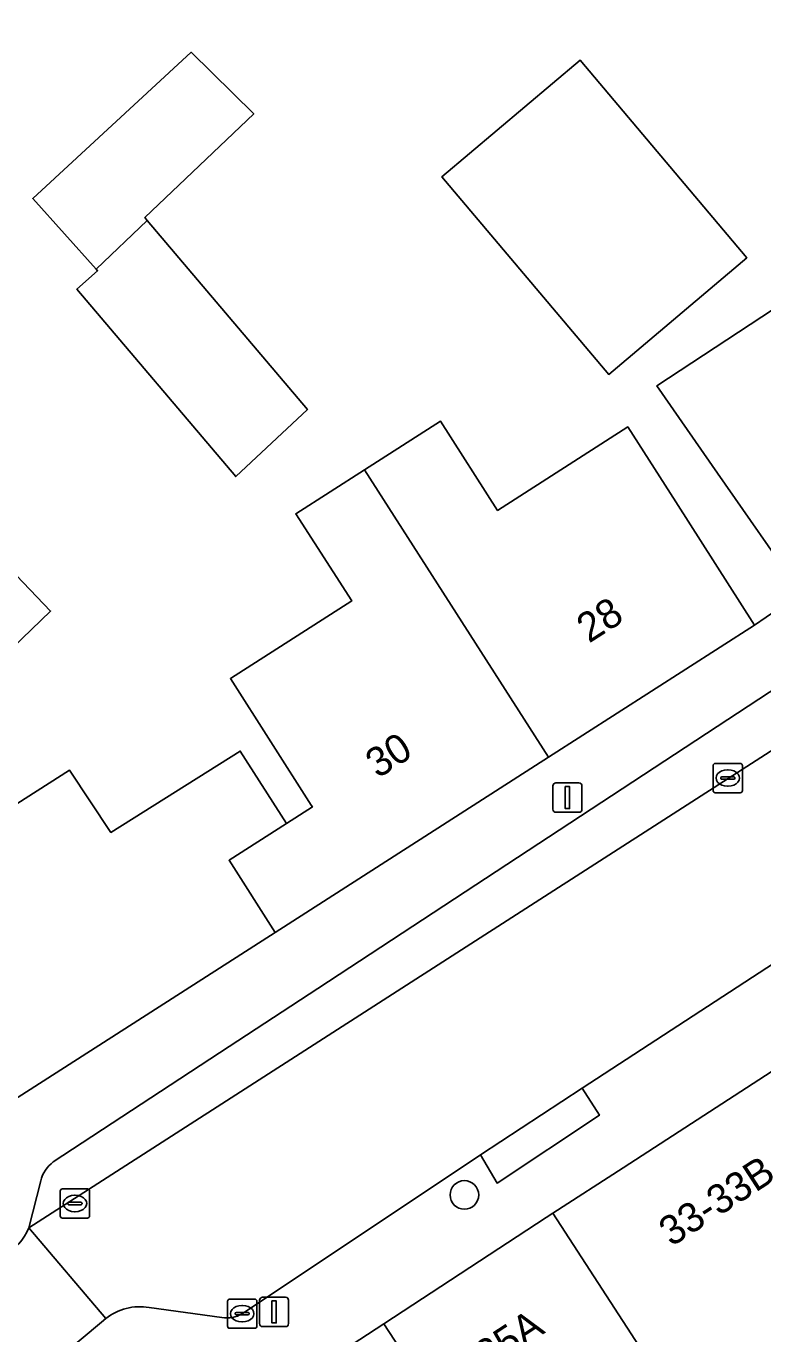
# Model space of a CAD drawing. Extents: x 161772 to 163126, y 383092 to 383917.
# Drawn here: x 162247.58 to 162272.75, y 383341.19 to 383385.86 of the extents above; entities that cross this region are included whole.
import ezdxf

# ---------------------------------------------------------------- set-up
doc = ezdxf.new("R2010")
doc.units = 0
for name, color, linetype in [('IMGEO_Boom', 7, 'Continuous'), ('IMGEO_Erf', 7, 'Continuous'), ('IMGEO_Kolk', 7, 'Continuous'), ('IMGEO_Lichtmast', 7, 'Continuous'), ('IMGEO_Pand', 7, 'Continuous'), ('IMGEO_Pand_nummerreeks', 7, 'Continuous'), ('IMGEO_Parkeervlak_open', 7, 'Continuous'), ('IMGEO_Rijbaan_lokaal_open', 7, 'Continuous'), ('IMGEO_Voetpad_open', 7, 'Continuous')]:
    doc.layers.add(name, color=color, linetype=linetype)

msp = doc.modelspace()

# ---------------------------------------------------------------- linework, layer by layer
at = {"layer": 'IMGEO_Boom'}
msp.add_circle((162262.557, 383345.937), 0.489, dxfattribs=at)
at = {"layer": 'IMGEO_Erf'}
for points in [[(162253.226, 383384.97), (162255.362, 383382.868), (162251.638, 383379.324), (162251.719, 383379.228), (162257.195, 383372.769), (162254.746, 383370.474), (162249.318, 383376.881), (162250.022, 383377.509), (162249.974, 383377.564), (162247.811, 383379.978)], [(162266.507, 383384.701), (162272.205, 383377.953), (162267.486, 383373.968), (162261.787, 383380.716)], [(162243.444, 383371.066), (162245.614, 383368.806), (162247.017, 383367.345), (162248.42, 383365.883), (162244.848, 383362.453), (162245.165, 383362.122), (162242.866, 383359.915), (162239.259, 383356.452), (162233.964, 383361.967), (162237.572, 383365.43), (162238.289, 383366.119)]]:
    msp.add_lwpolyline(points, close=True, dxfattribs=at)
msp.add_lwpolyline([(162246.15, 383358.588), (162249.06, 383360.453), (162250.478, 383358.321), (162254.9, 383361.102), (162256.478, 383358.625), (162257.361, 383359.19), (162257.323, 383359.251), (162254.561, 383363.573), (162258.706, 383366.228), (162256.796, 383369.209), (162259.141, 383370.711), (162261.734, 383372.372), (162263.689, 383369.321), (162268.136, 383372.17), (162269.776, 383369.611), (162272.473, 383365.4), (162274.058, 383366.492), (162271.202, 383370.596), (162269.13, 383373.573), (162276.666, 383378.534)], dxfattribs=at)
at = {"layer": 'IMGEO_Kolk'}
for p, q in [((162271.054, 383359.752), (162271.054, 383360.604)), ((162271.129, 383360.678), (162271.981, 383360.678)), ((162271.542, 383360.458), (162271.567, 383360.458)), ((162272.055, 383360.604), (162272.055, 383359.752)), ((162271.313, 383360.172), (162271.313, 383360.184)), ((162271.751, 383360.135), (162271.353, 383360.135)), ((162271.356, 383360.221), (162271.754, 383360.221)), ((162271.797, 383360.184), (162271.797, 383360.172)), ((162271.981, 383359.678), (162271.129, 383359.678)), ((162271.565, 383359.898), (162271.54, 383359.898)), ((162248.825, 383346.145), (162249.677, 383346.145)), ((162248.75, 383345.219), (162248.75, 383346.071)), ((162249.009, 383345.639), (162249.009, 383345.651)), ((162249.052, 383345.688), (162249.45, 383345.688)), ((162249.238, 383345.925), (162249.263, 383345.925)), ((162249.493, 383345.651), (162249.493, 383345.639)), ((162249.751, 383346.071), (162249.751, 383345.219)), ((162249.447, 383345.602), (162249.049, 383345.602)), ((162249.261, 383345.365), (162249.236, 383345.365)), ((162249.677, 383345.145), (162248.825, 383345.145)), ((162254.464, 383341.456), (162254.464, 383342.308)), ((162254.539, 383342.382), (162255.391, 383342.382)), ((162254.952, 383342.162), (162254.977, 383342.162)), ((162255.465, 383342.308), (162255.465, 383341.456)), ((162254.723, 383341.876), (162254.723, 383341.888)), ((162255.161, 383341.839), (162254.763, 383341.839)), ((162254.766, 383341.925), (162255.164, 383341.925)), ((162255.207, 383341.888), (162255.207, 383341.876)), ((162255.391, 383341.382), (162254.539, 383341.382)), ((162254.975, 383341.602), (162254.95, 383341.602))]:
    msp.add_line(p, q, dxfattribs=at)
for points in [[(162271.054, 383359.752), (162271.054, 383360.604)], [(162271.129, 383360.678), (162271.981, 383360.678)], [(162272.055, 383360.604), (162272.055, 383359.752)], [(162271.981, 383359.678), (162271.129, 383359.678)], [(162248.825, 383346.145), (162249.677, 383346.145)], [(162248.75, 383345.219), (162248.75, 383346.071)], [(162249.751, 383346.071), (162249.751, 383345.219)], [(162249.677, 383345.145), (162248.825, 383345.145)], [(162254.464, 383341.456), (162254.464, 383342.308)], [(162254.539, 383342.382), (162255.391, 383342.382)], [(162255.465, 383342.308), (162255.465, 383341.456)], [(162255.391, 383341.382), (162254.539, 383341.382)]]:
    msp.add_lwpolyline(points, dxfattribs=at)
for centre, radius, start, end in [((162271.131, 383360.602), 0.0765, 91.552, 178.448), ((162271.131, 383360.602), 0.0765, 91.552, 178.448), ((162271.979, 383360.602), 0.0765, 1.552, 88.448), ((162271.979, 383360.602), 0.0765, 1.552, 88.448), ((162271.353, 383360.181), 0.0403, 85.8775, 175.7526), ((162271.35, 383360.171), 0.0366, 178.938, 274.7102), ((162271.754, 383360.178), 0.043, 264.8664, 352.4533), ((162271.758, 383360.183), 0.0386, 1.7309, 96.639), ((162271.131, 383359.754), 0.0765, 181.552, 268.448), ((162271.131, 383359.754), 0.0765, 181.552, 268.448), ((162271.979, 383359.754), 0.0765, 271.552, 358.448), ((162271.979, 383359.754), 0.0765, 271.552, 358.448), ((162248.827, 383346.069), 0.0765, 91.552, 178.448), ((162248.827, 383346.069), 0.0765, 91.552, 178.448), ((162249.675, 383346.069), 0.0765, 1.552, 88.448), ((162249.675, 383346.069), 0.0765, 1.552, 88.448), ((162249.049, 383345.648), 0.0403, 85.8775, 175.7526), ((162249.046, 383345.638), 0.0366, 178.938, 274.7102), ((162249.45, 383345.645), 0.043, 264.8664, 352.4533), ((162249.454, 383345.65), 0.0386, 1.7309, 96.639), ((162248.827, 383345.221), 0.0765, 181.552, 268.448), ((162248.827, 383345.221), 0.0765, 181.552, 268.448), ((162249.675, 383345.221), 0.0765, 271.552, 358.448), ((162249.675, 383345.221), 0.0765, 271.552, 358.448), ((162254.541, 383342.306), 0.0765, 91.552, 178.448), ((162254.541, 383342.306), 0.0765, 91.552, 178.448), ((162255.389, 383342.306), 0.0765, 1.552, 88.448), ((162255.389, 383342.306), 0.0765, 1.552, 88.448), ((162254.763, 383341.885), 0.0403, 85.8775, 175.7526), ((162254.76, 383341.875), 0.0366, 178.938, 274.7102), ((162255.164, 383341.882), 0.043, 264.8664, 352.4533), ((162255.168, 383341.887), 0.0386, 1.7309, 96.639), ((162254.541, 383341.458), 0.0765, 181.552, 268.448), ((162254.541, 383341.458), 0.0765, 181.552, 268.448), ((162255.389, 383341.458), 0.0765, 271.552, 358.448), ((162255.389, 383341.458), 0.0765, 271.552, 358.448)]:
    msp.add_arc(centre, radius, start, end, dxfattribs=at)
for centre, major_axis, ratio, start_param, end_param in [((162271.541, 383360.178), (-0.387, 0.002), 0.722429, 4.712389, 7.853982), ((162271.566, 383360.178), (-0.39, 0.002), 0.717154, 1.570796, 4.712389), ((162249.237, 383345.645), (-0.387, 0.002), 0.722429, 4.712389, 7.853982), ((162249.262, 383345.645), (-0.39, 0.002), 0.717154, 1.570796, 4.712389), ((162254.951, 383341.882), (-0.387, 0.002), 0.722429, 4.712389, 7.853982), ((162254.976, 383341.882), (-0.39, 0.002), 0.717154, 1.570796, 4.712389)]:
    msp.add_ellipse(centre, major_axis=major_axis, ratio=ratio, start_param=start_param, end_param=end_param, dxfattribs=at)
at = {"layer": 'IMGEO_Lichtmast'}
for p, q in [((162265.681, 383360.01), (162266.471, 383360.01)), ((162266.471, 383360.01), (162265.681, 383360.01)), ((162265.581, 383359.11), (162265.581, 383359.91)), ((162265.581, 383359.91), (162265.581, 383359.11)), ((162266.571, 383359.91), (162266.571, 383359.11)), ((162266.571, 383359.11), (162266.571, 383359.91)), ((162266.471, 383359.01), (162265.681, 383359.01)), ((162265.681, 383359.01), (162266.471, 383359.01)), ((162255.558, 383341.541), (162255.558, 383342.341)), ((162255.558, 383342.341), (162255.558, 383341.541)), ((162255.658, 383342.441), (162256.448, 383342.441)), ((162256.448, 383342.441), (162255.658, 383342.441)), ((162256.548, 383342.341), (162256.548, 383341.541)), ((162256.548, 383341.541), (162256.548, 383342.341)), ((162256.448, 383341.441), (162255.658, 383341.441)), ((162255.658, 383341.441), (162256.448, 383341.441))]:
    msp.add_line(p, q, dxfattribs=at)
for points in [[(162266.001, 383359.885), (162266.151, 383359.885), (162266.151, 383359.135), (162266.001, 383359.135), (162266.001, 383359.885)], [(162255.978, 383342.316), (162256.128, 383342.316), (162256.128, 383341.566), (162255.978, 383341.566), (162255.978, 383342.316)]]:
    msp.add_lwpolyline(points, dxfattribs=at)
for centre, start, end in [((162265.681, 383359.91), 90, 180), ((162265.681, 383359.91), 90, 180), ((162266.471, 383359.91), 0, 90), ((162266.471, 383359.91), 360, 90), ((162265.681, 383359.11), 180, 270), ((162265.681, 383359.11), 180, 270), ((162266.471, 383359.11), 270, 0), ((162266.471, 383359.11), 270, 0), ((162255.658, 383342.341), 90, 180), ((162255.658, 383342.341), 90, 180), ((162256.448, 383342.341), 0, 90), ((162256.448, 383342.341), 360, 90), ((162255.658, 383341.541), 180, 270), ((162255.658, 383341.541), 180, 270), ((162256.448, 383341.541), 270, 0), ((162256.448, 383341.541), 270, 0)]:
    msp.add_arc(centre, 0.1, start, end, dxfattribs=at)
at = {"layer": 'IMGEO_Pand'}
for points in [[(162249.974, 383377.564), (162251.719, 383379.228), (162251.638, 383379.324), (162255.362, 383382.868), (162253.226, 383384.97), (162247.811, 383379.978)], [(162267.486, 383373.968), (162272.205, 383377.953), (162266.507, 383384.701), (162261.787, 383380.716)], [(162249.974, 383377.564), (162250.022, 383377.509), (162249.318, 383376.881), (162254.746, 383370.474), (162257.195, 383372.769), (162251.719, 383379.228)], [(162279.486, 383374.316), (162276.955, 383378.161), (162276.666, 383378.534), (162269.13, 383373.573), (162271.202, 383370.596), (162274.058, 383366.492), (162281.53, 383371.212)], [(162265.432, 383360.889), (162272.473, 383365.4), (162269.776, 383369.611), (162268.136, 383372.17), (162263.689, 383369.321), (162261.734, 383372.372), (162259.141, 383370.711)], [(162245.165, 383362.122), (162244.848, 383362.453), (162248.42, 383365.883), (162247.017, 383367.345), (162245.614, 383368.806), (162243.444, 383371.066), (162238.289, 383366.119), (162237.572, 383365.43), (162233.964, 383361.967), (162239.259, 383356.452), (162242.866, 383359.915)], [(162259.141, 383370.711), (162256.796, 383369.209), (162258.706, 383366.228), (162254.561, 383363.573), (162257.323, 383359.251), (162257.361, 383359.19), (162256.478, 383358.625), (162254.519, 383357.371), (162256.096, 383354.907), (162265.432, 383360.889)], [(162256.478, 383358.625), (162254.9, 383361.102), (162250.478, 383358.321), (162249.06, 383360.453), (162246.15, 383358.588), (162240.626, 383355.049), (162245.995, 383349.427), (162247.147, 383349.174), (162256.096, 383354.907), (162254.519, 383357.371)], [(162273.27, 383350.29), (162267.982, 383346.867), (162265.576, 383345.313), (162270.362, 383337.946), (162272.569, 383339.386), (162275.024, 383335.763), (162276.007, 383334.264), (162279.166, 383336.333), (162281.626, 383337.944), (162281.137, 383338.698), (162280.649, 383339.452)], [(162268.478, 383336.717), (162268.836, 383336.95), (162270.362, 383337.946), (162265.576, 383345.313), (162265.346, 383345.166), (162259.802, 383341.536), (162267.119, 383330.346), (162267.972, 383329.029), (162270.071, 383325.787), (162271.515, 383324.106), (162273.769, 383326.031), (162274.339, 383326.466), (162271.249, 383331.172), (162270.66, 383331.129), (162269.2, 383333.319), (162270.276, 383334.021)], [(162259.802, 383341.536), (162253.701, 383337.545), (162253.9, 383337.318), (162262.568, 383327.401), (162267.119, 383330.346)]]:
    msp.add_lwpolyline(points, close=True, dxfattribs=at)
at = {"layer": 'IMGEO_Parkeervlak_open'}
for points in [[(162247.678, 383344.816), (162294.06, 383374.608)], [(162281.593, 383368.76), (162257.543, 383352.991)], [(162257.543, 383352.991), (162254.518, 383351.008)], [(162254.518, 383351.008), (162248.509, 383347.068)], [(162248.086, 383346.419), (162247.678, 383344.816)]]:
    msp.add_lwpolyline(points, dxfattribs=at)
msp.add_arc((162249.166, 383346.178), 1.106, 126.408, 167.4017, dxfattribs=at)
at = {"layer": 'IMGEO_Rijbaan_lokaal_open'}
for points in [[(162354.163, 383426.013), (162352.175, 383424.284), (162348.197, 383420.829), (162337.817, 383411.925), (162336.645, 383410.915), (162332.617, 383407.444), (162321.815, 383398.151), (162317.816, 383394.703), (162314.712, 383392.04), (162310.37, 383388.302), (162309.749, 383387.68), (162297.572, 383377.466), (162294.06, 383374.608), (162247.678, 383344.816), (162250.301, 383341.713)], [(162263.102, 383347.309), (162266.585, 383349.589), (162273.903, 383354.359), (162280.472, 383358.642), (162288.762, 383364.047), (162289.496, 383364.525), (162292.841, 383366.706), (162295.846, 383368.569), (162297.678, 383369.705), (162302.316, 383372.966), (162307.742, 383378.84), (162312.426, 383383.912), (162313.87, 383385.476), (162314.36, 383385.9), (162346.097, 383413.353)], [(162254.965, 383341.882), (162263.102, 383347.309)], [(162238.381, 383333.192), (162248.767, 383340.426), (162250.161, 383341.595), (162250.301, 383341.713), (162247.678, 383344.816)], [(162251.787, 383342.096), (162254.268, 383341.757)]]:
    msp.add_lwpolyline(points, dxfattribs=at)
for centre, radius, start, end in [((162245.851, 383345.597), 1.987, 299.2852, 336.8602), ((162251.479, 383340.218), 1.903, 80.6758, 128.2298), ((162254.461, 383342.684), 0.947, 258.2221, 302.1126)]:
    msp.add_arc(centre, radius, start, end, dxfattribs=at)
at = {"layer": 'IMGEO_Voetpad_open'}
for points in [[(162253.701, 383337.545), (162259.802, 383341.536), (162265.346, 383345.166), (162265.576, 383345.313), (162267.982, 383346.867), (162273.27, 383350.29), (162277.606, 383353.097), (162280.334, 383354.918), (162286.046, 383358.641), (162293.817, 383363.705), (162293.909, 383363.765), (162299.693, 383367.539), (162300.246, 383366.973), (162303.367, 383369.986), (162303.684, 383369.717), (162307.098, 383372.957), (162310.48, 383376.63), (162315.096, 383381.379), (162318.405, 383382.124), (162328.478, 383391.862)], [(162314.36, 383385.9), (162313.87, 383385.476), (162312.426, 383383.912), (162313.161, 383383.294), (162308.468, 383378.157), (162307.742, 383378.84), (162302.316, 383372.966), (162297.678, 383369.705), (162295.846, 383368.569), (162296.355, 383367.718), (162289.304, 383363.189), (162288.762, 383364.047), (162280.472, 383358.642), (162281.061, 383357.705), (162274.467, 383353.437), (162273.903, 383354.359), (162266.585, 383349.589), (162267.167, 383348.658), (162263.674, 383346.344), (162263.102, 383347.309), (162254.965, 383341.882)], [(162297.545, 383380.677), (162296.373, 383382.529), (162295.862, 383382.133), (162293.293, 383380.139), (162284.036, 383372.968), (162281.53, 383371.212), (162274.058, 383366.492), (162272.473, 383365.4), (162265.432, 383360.889), (162256.096, 383354.907), (162247.147, 383349.174), (162243.372, 383346.601), (162240.594, 383344.436)], [(162248.509, 383347.068), (162254.518, 383351.008), (162257.543, 383352.991), (162281.593, 383368.76), (162280.952, 383369.701)], [(162247.678, 383344.816), (162248.086, 383346.419)], [(162254.268, 383341.757), (162251.787, 383342.096)], [(162250.301, 383341.713), (162250.161, 383341.595), (162248.767, 383340.426)]]:
    msp.add_lwpolyline(points, dxfattribs=at)
msp.add_lwpolyline([(162263.102, 383347.309), (162263.674, 383346.344), (162267.167, 383348.658), (162266.585, 383349.589)], close=True, dxfattribs=at)
for centre, radius, start, end in [((162249.166, 383346.178), 1.106, 126.408, 167.4017), ((162245.851, 383345.597), 1.987, 299.2852, 336.8602), ((162251.479, 383340.218), 1.903, 80.6758, 128.2298), ((162254.461, 383342.684), 0.947, 258.2221, 302.1126)]:
    msp.add_arc(centre, radius, start, end, dxfattribs=at)

# ---------------------------------------------------------------- texts
at = {"layer": 'IMGEO_Pand_nummerreeks'}
for s, rotation, p in [('28', 32.6471, (162266.814, 383364.768)), ('30', 32.6471, (162259.602, 383360.146)), ('33-33B', 32.9164, (162269.63, 383344.152)), ('35-35A', 33.1914, (162261.741, 383338.885))]:
    msp.add_text(s, height=1, rotation=rotation, dxfattribs=at).set_placement(p)

doc.saveas('drawing.dxf')
